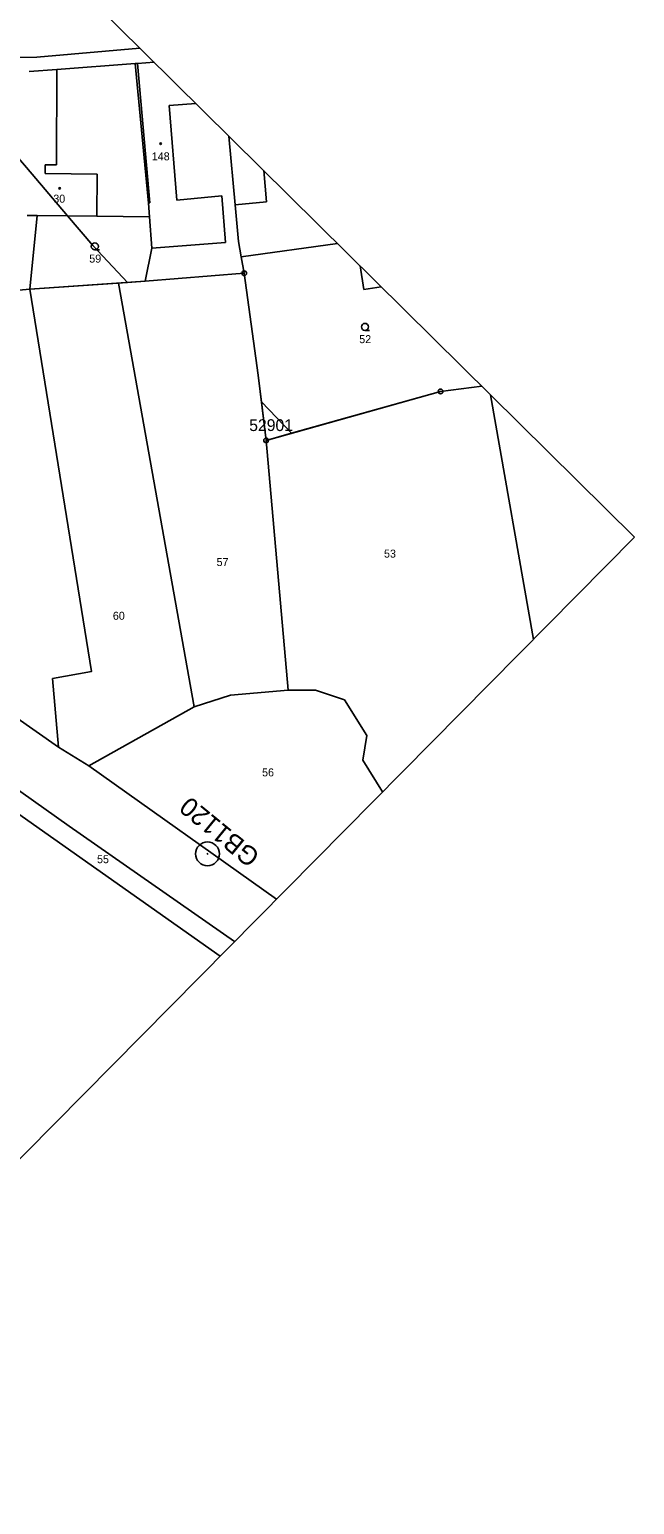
# Model space of a CAD drawing. Extents: x -777175 to -776673, y -1110537 to -1110036.
# Drawn here: x -776801.4 to -776672.9, y -1110537.2 to -1110223.9 of the extents above; entities that cross this region are included whole.
import ezdxf

# ---------------------------------------------------------------- set-up
doc = ezdxf.new("R2010")
doc.units = 0
for name, color, linetype in [('BPEJ', 7, 'Continuous'), ('Katastr_HRANICE DRÁHY', 7, 'Continuous'), ('Katastr_Hranice parcel', 7, 'Continuous'), ('Katastr_Parcelní čísla', 7, 'Continuous'), ('Katastr_Slučkované čáry', 7, 'Continuous'), ('Katastr_Značky kultur', 7, 'Continuous'), ('ŽBP', 7, 'Continuous')]:
    doc.layers.add(name, color=color, linetype=linetype)

msp = doc.modelspace()

# ---------------------------------------------------------------- linework, layer by layer
at = {"layer": 'BPEJ'}
for points in [[(-776852.23, -1110181.54), (-776851.73, -1110182.33), (-776845.13, -1110192.18), (-776842.54, -1110196.21), (-776837.7, -1110203.74), (-776836.65, -1110205.62), (-776829.07, -1110219.13), (-776827.66, -1110221.2), (-776826.66, -1110222.65), (-776822.05, -1110229.41), (-776821.58, -1110229.97), (-776818.14, -1110234.08), (-776814.62, -1110238.29), (-776805.87, -1110248.74), (-776802.05, -1110253.25), (-776793.36, -1110263.5)], [(-776793.36, -1110263.5), (-776788.02, -1110269.8), (-776780.63, -1110277.66)], [(-776752.19, -1110303.01), (-776752.89, -1110297.34), (-776755.83, -1110275.7), (-776776.85, -1110277.4), (-776780.63, -1110277.66)], [(-776705.36, -1110299.69), (-776714.14, -1110300.8), (-776745.76, -1110309.67)], [(-776745.76, -1110309.67), (-776751.19, -1110311.2), (-776752.19, -1110303.01)], [(-776752.19, -1110303.01), (-776745.76, -1110309.67)]]:
    msp.add_lwpolyline(points, dxfattribs=at)
at = {"layer": 'Defpoints'}
for p, q in [((-776672.94, -1110331.74), (-776971.6, -1110036.44)), ((-776876.14, -1110537.25), (-776672.94, -1110331.74))]:
    msp.add_line(p, q, dxfattribs=at)
at = {"layer": 'Katastr_HRANICE DRÁHY'}
for points in [[(-776757.91, -1110417.68), (-776792.98, -1110393.16), (-776846.61, -1110355.09), (-776904.52, -1110315.47), (-776922.51, -1110314.75), (-776940.41, -1110317.34)], [(-776849.62, -1110338.22), (-776813.64, -1110363.55), (-776795.25, -1110376.34), (-776788.84, -1110380.33), (-776748.99, -1110408.66)]]:
    msp.add_lwpolyline(points, dxfattribs=at)
at = {"layer": 'Katastr_Hranice parcel'}
msp.add_line((-776766.43, -1110367.83), (-776782.5, -1110277.79), dxfattribs=at)
for points in [[(-776799.9, -1110229.78), (-776777.97, -1110227.9)], [(-776830.22, -1110230.05), (-776799.9, -1110229.78)], [(-776779.02, -1110231.14), (-776795.61, -1110232.41)], [(-776778.51, -1110231.13), (-776779.02, -1110231.14)], [(-776779.02, -1110231.14), (-776776.18, -1110260.79)], [(-776778.51, -1110231.13), (-776774.98, -1110230.85)], [(-776801.53, -1110232.8), (-776795.61, -1110232.41)], [(-776759.09, -1110246.56), (-776757.74, -1110261.17)], [(-776775.96, -1110263.73), (-776776.18, -1110260.79)], [(-776757.04, -1110268.94), (-776757.74, -1110261.17)], [(-776799.81, -1110263.42), (-776801.9, -1110263.39)], [(-776801.34, -1110279.1), (-776799.81, -1110263.42)], [(-776787.15, -1110263.58), (-776799.81, -1110263.42)], [(-776775.96, -1110263.73), (-776787.15, -1110263.58)], [(-776775.96, -1110263.73), (-776775.44, -1110270.36)], [(-776780.63, -1110277.66), (-776801.34, -1110279.1), (-776814.49, -1110280.25), (-776823.89, -1110281.93), (-776826.29, -1110267.5), (-776831.4, -1110267.85), (-776830.95, -1110273.53), (-776856.55, -1110275.29), (-776856.32, -1110281.19), (-776854.31, -1110299.08), (-776849.62, -1110338.22), (-776894.76, -1110305.65), (-776896.59, -1110304.32), (-776903.91, -1110299.01), (-776906.52, -1110296.78), (-776914.36, -1110290.06), (-776923.15, -1110282.87), (-776931.82, -1110275.9)], [(-776756.46, -1110272.21), (-776757.04, -1110268.94)], [(-776776.85, -1110277.4), (-776775.44, -1110270.36)], [(-776756.46, -1110272.21), (-776736.03, -1110269.37)], [(-776755.83, -1110275.7), (-776756.46, -1110272.21)], [(-776730.4, -1110279.14), (-776731.19, -1110274.15)], [(-776776.85, -1110277.4), (-776801.34, -1110279.1)], [(-776755.83, -1110275.7), (-776776.85, -1110277.4)], [(-776752.89, -1110297.34), (-776755.83, -1110275.7)], [(-776801.34, -1110279.1), (-776814.49, -1110280.25)], [(-776795.25, -1110376.34), (-776796.53, -1110361.81), (-776788.29, -1110360.31), (-776801.34, -1110279.1)], [(-776730.4, -1110279.14), (-776726.73, -1110278.56)], [(-776751.19, -1110311.2), (-776752.89, -1110297.34)], [(-776705.36, -1110299.69), (-776714.14, -1110300.8)], [(-776714.14, -1110300.8), (-776751.19, -1110311.2)], [(-776694.41, -1110353.46), (-776703.54, -1110301.49)], [(-776726.46, -1110385.87), (-776730.62, -1110379.11), (-776729.8, -1110373.88), (-776734.55, -1110366.33), (-776740.71, -1110364.29), (-776746.53, -1110364.29), (-776751.19, -1110311.2)], [(-776848.72, -1110358.87), (-776760.96, -1110420.76)], [(-776746.53, -1110364.29), (-776758.73, -1110365.29), (-776766.43, -1110367.83), (-776788.84, -1110380.33)]]:
    msp.add_lwpolyline(points, dxfattribs=at)
at = {"layer": 'Katastr_Slučkované čáry'}
for points in [[(-776778.51, -1110231.13), (-776775.88, -1110260.76)], [(-776795.61, -1110232.41), (-776795.71, -1110252.68)], [(-776771.77, -1110240.07), (-776766.11, -1110239.62)], [(-776771.77, -1110240.07), (-776770.17, -1110260.2)], [(-776798.13, -1110254.47), (-776798.12, -1110252.66)], [(-776798.12, -1110252.66), (-776795.71, -1110252.68)], [(-776787.03, -1110254.61), (-776798.13, -1110254.47)], [(-776787.15, -1110263.58), (-776787.03, -1110254.61)], [(-776751.69, -1110253.88), (-776751.07, -1110260.55)], [(-776760.58, -1110259.26), (-776770.17, -1110260.2)], [(-776759.81, -1110269.15), (-776760.58, -1110259.26)], [(-776776.18, -1110260.79), (-776775.88, -1110260.76)], [(-776751.07, -1110260.55), (-776757.74, -1110261.17)], [(-776775.44, -1110270.36), (-776759.81, -1110269.15)]]:
    msp.add_lwpolyline(points, dxfattribs=at)
at = {"layer": 'Katastr_Značky kultur'}
for p, q in [((-776787.56, -1110270.73), (-776786.56, -1110270.73)), ((-776755.88, -1110275.7), (-776755.78, -1110275.7)), ((-776730.19, -1110287.84), (-776729.19, -1110287.84)), ((-776714.19, -1110300.8), (-776714.09, -1110300.8)), ((-776751.24, -1110311.2), (-776751.14, -1110311.2))]:
    msp.add_line(p, q, dxfattribs=at)
for centre, radius in [((-776773.57, -1110248.17), 0.175), ((-776795.04, -1110257.66), 0.175), ((-776787.56, -1110269.98), 0.75), ((-776755.83, -1110275.7), 0.499), ((-776730.19, -1110287.09), 0.75), ((-776714.14, -1110300.8), 0.499), ((-776751.19, -1110311.2), 0.499)]:
    msp.add_circle(centre, radius, dxfattribs=at)
at = {"layer": 'ŽBP'}
msp.add_line((-776763.71, -1110398.88), (-776763.56, -1110399.18), dxfattribs=at)
msp.add_circle((-776763.63, -1110399.03), 2.52, dxfattribs=at)

# ---------------------------------------------------------------- texts
at = {"layer": 'BPEJ'}
msp.add_text('52901', height=2.5, dxfattribs=at).set_placement((-776754.77, -1110309.21))
at = {"layer": 'Katastr_Parcelní čísla'}
for s, p in [('148', (-776775.46, -1110251.7)), ('30', (-776796.38, -1110260.7)), ('59', (-776788.74, -1110273.43)), ('52', (-776731.4, -1110290.54)), ('53', (-776726.14, -1110336.1)), ('57', (-776761.7, -1110337.88)), ('60', (-776783.73, -1110349.3)), ('56', (-776752.04, -1110382.57)), ('55', (-776787.09, -1110401.01))]:
    msp.add_text(s, height=1.7, dxfattribs=at).set_placement(p)
at = {"layer": 'ŽBP'}
msp.add_text('GB1120', height=4, rotation=140.7132, dxfattribs=at).set_placement((-776752.23, -1110399.07))

doc.saveas('drawing.dxf')
